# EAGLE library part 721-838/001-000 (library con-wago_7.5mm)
Serie 721, Stiftleiste mit abgewinkelten Einlötstiften / Series 721, Male connector with angled solder pins Polzahl / Pole No.: 8 Rastermaß / Pitch: 7.5 mm Bemessungsspannung / Rated Voltage: 630 V Nennstrom / Nominal Current: 12 A Lötstiftlänge: / Solder Pin Length: 3.8 mm Farbe / Color: lichtgrau / light gray Stand: 01.01.2012. Die jeweils aktuellen Daten zu diesem Artikel finden Sie in unserem Produktkatalog, den Sie unter www.wago.com einsehen können. As of: 01/01/2012. Please find the newest data for this article in our product catalogue, which can be viewed under www.wago.com.
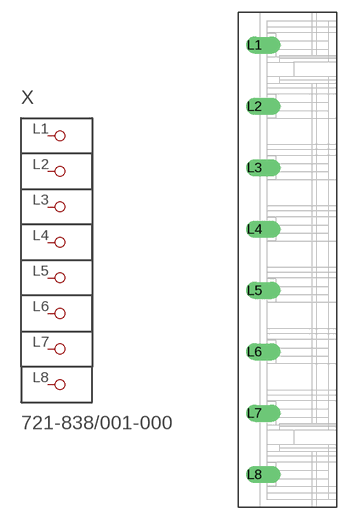
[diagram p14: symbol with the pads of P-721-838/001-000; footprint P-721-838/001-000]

Designator prefix X

## 721-838/001-000  [P-721-838/001-000]
L1  P1
L2  P2
L3  P3
L4  P4
L5  P5
L6  P6
L7  P7
L8  P8

## Footprint P-721-838/001-000 (pad centres in mm)
drill 1.4 offset: L1 -4,26.25; L2 -4,18.75; L3 -4,11.25; L4 -4,3.75; L5 -4,-3.75; L6 -4,-11.25; L7 -4,-18.75; L8 -4,-26.25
